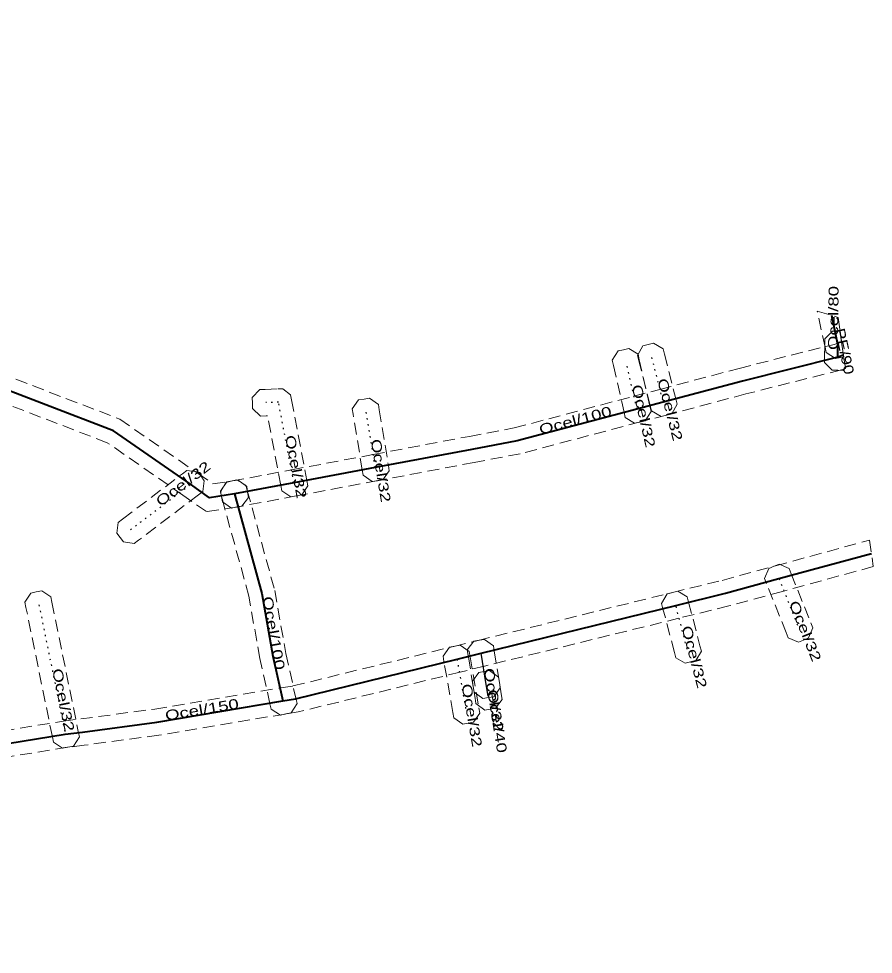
# Model space of a CAD drawing. Extents: x -583333 to -583115, y -1209681 to -1209498.
# Drawn here: x -583179.8 to -583115.3, y -1209573.7 to -1209503.1 of the extents above; entities that cross this region are included whole.
import ezdxf

# ---------------------------------------------------------------- set-up
doc = ezdxf.new("R2010")
doc.units = 0
doc.header["$LTSCALE"] = 0.3
doc.linetypes.add('DOTTED', pattern=[1.5, 0.3, -1.2])
doc.linetypes.add('MEDIUM_DASHED', pattern=[4.5, 3, -1.5])
for name, color, linetype, lineweight in [('1', 7, 'MEDIUM_DASHED', 13), ('14', 7, 'Continuous', 40), ('18', 7, 'DOTTED', 25)]:
    doc.layers.add(name, color=color, linetype=linetype, lineweight=lineweight)
doc.layers.add('20', color=7, linetype='Continuous')

msp = doc.modelspace()

# ---------------------------------------------------------------- linework, layer by layer
at = {"layer": '1'}
for points in [[(-583117.931, -1209525.643), (-583117.511, -1209528.621), (-583117.729, -1209528.668), (-583118.134, -1209528.755), (-583118.831, -1209528.306), (-583118.918, -1209527.901), (-583119.505, -1209525.173)], [(-583117.783, -1209526.692), (-583117.388, -1209529.489), (-583117.547, -1209529.644), (-583117.961, -1209529.64), (-583118.375, -1209529.635), (-583118.954, -1209529.043), (-583118.95, -1209528.629), (-583118.94, -1209527.679), (-583118.935, -1209527.265), (-583118.343, -1209526.686), (-583117.929, -1209526.69)], [(-583118.234, -1209527.68), (-583117.671, -1209527.488), (-583117.386, -1209529.504), (-583117.666, -1209529.6), (-583124.899, -1209531.428), (-583130.894, -1209533.017), (-583132.864, -1209533.537), (-583141.95, -1209535.946), (-583145.405, -1209536.593), (-583152.695, -1209537.973), (-583158.846, -1209539.123), (-583163.326, -1209539.963), (-583163.733, -1209540.039), (-583164.417, -1209539.571), (-583164.493, -1209539.164), (-583164.569, -1209538.757), (-583164.101, -1209538.073), (-583163.694, -1209537.997), (-583159.214, -1209537.157), (-583153.065, -1209536.007), (-583145.775, -1209534.627), (-583142.39, -1209533.994), (-583133.376, -1209531.603), (-583131.406, -1209531.083), (-583125.401, -1209529.492)], [(-583134.003, -1209533.196), (-583134.095, -1209532.792), (-583134.895, -1209529.282), (-583134.987, -1209528.878), (-583134.546, -1209528.177), (-583134.142, -1209528.085), (-583133.738, -1209527.993), (-583133.037, -1209528.434), (-583132.945, -1209528.838), (-583132.145, -1209532.348), (-583132.053, -1209532.752), (-583132.494, -1209533.453), (-583132.898, -1209533.545), (-583133.302, -1209533.637)], [(-583131.155, -1209528.02), (-583131.052, -1209528.421), (-583130.182, -1209531.801), (-583130.078, -1209532.202), (-583130.5, -1209532.915), (-583130.901, -1209533.018), (-583131.302, -1209533.122), (-583132.015, -1209532.7), (-583132.118, -1209532.299), (-583132.988, -1209528.919), (-583133.092, -1209528.518), (-583132.67, -1209527.805), (-583132.269, -1209527.702), (-583131.868, -1209527.598)], [(-583159.935, -1209538.734), (-583160.012, -1209538.327), (-583161.013, -1209533.076), (-583161.129, -1209533.08), (-583161.543, -1209533.092), (-583162.147, -1209532.525), (-583162.16, -1209532.111), (-583162.172, -1209531.697), (-583161.605, -1209531.093), (-583161.191, -1209531.08), (-583160.221, -1209531.05), (-583159.852, -1209531.039), (-583159.277, -1209531.501), (-583159.208, -1209531.863), (-583158.048, -1209537.953), (-583157.971, -1209538.36), (-583158.436, -1209539.045), (-583158.843, -1209539.122), (-583159.25, -1209539.199)], [(-583153.799, -1209537.561), (-583153.867, -1209537.152), (-583154.557, -1209532.962), (-583154.624, -1209532.554), (-583154.141, -1209531.881), (-583153.732, -1209531.813), (-583153.324, -1209531.746), (-583152.651, -1209532.229), (-583152.583, -1209532.638), (-583151.893, -1209536.828), (-583151.826, -1209537.236), (-583152.309, -1209537.909), (-583152.718, -1209537.977), (-583153.126, -1209538.044)], [(-583172.294, -1209541.123), (-583171.963, -1209540.873), (-583167.443, -1209537.453), (-583167.113, -1209537.203), (-583166.293, -1209537.316), (-583166.043, -1209537.647), (-583165.793, -1209537.977), (-583165.906, -1209538.797), (-583166.237, -1209539.047), (-583170.757, -1209542.467), (-583171.087, -1209542.717), (-583171.907, -1209542.604), (-583172.157, -1209542.273), (-583172.407, -1209541.943)], [(-583162.655, -1209538.316), (-583162.546, -1209538.715), (-583160.473, -1209546.271), (-583159.639, -1209551.024), (-583158.884, -1209554.391), (-583158.793, -1209554.795), (-583159.237, -1209555.495), (-583159.641, -1209555.586), (-583160.045, -1209555.677), (-583160.745, -1209555.233), (-583160.836, -1209554.829), (-583161.601, -1209551.416), (-583162.427, -1209546.709), (-583164.474, -1209539.245), (-583164.584, -1209538.845), (-583164.174, -1209538.125), (-583163.775, -1209538.016), (-583163.375, -1209537.906)], [(-583121.625, -1209544.615), (-583121.471, -1209544.999), (-583119.991, -1209548.709), (-583119.838, -1209549.094), (-583120.165, -1209549.855), (-583120.549, -1209550.009), (-583120.934, -1209550.162), (-583121.695, -1209549.835), (-583121.849, -1209549.451), (-583123.329, -1209545.741), (-583123.482, -1209545.356), (-583123.155, -1209544.595), (-583122.771, -1209544.441), (-583122.386, -1209544.288)], [(-583177.383, -1209546.754), (-583177.3, -1209547.16), (-583175.31, -1209556.92), (-583175.227, -1209557.326), (-583175.684, -1209558.017), (-583176.09, -1209558.1), (-583176.496, -1209558.183), (-583177.187, -1209557.726), (-583177.27, -1209557.32), (-583179.26, -1209547.56), (-583179.343, -1209547.154), (-583178.886, -1209546.463), (-583178.48, -1209546.38), (-583178.074, -1209546.297)], [(-583130.193, -1209551.343), (-583130.298, -1209550.942), (-583131.158, -1209547.642), (-583131.262, -1209547.241), (-583130.843, -1209546.527), (-583130.442, -1209546.422), (-583130.041, -1209546.318), (-583129.327, -1209546.737), (-583129.222, -1209547.138), (-583128.362, -1209550.438), (-583128.258, -1209550.839), (-583128.677, -1209551.553), (-583129.078, -1209551.658), (-583129.479, -1209551.762)], [(-583145.796, -1209550.88), (-583145.725, -1209551.288), (-583145.055, -1209555.128), (-583144.984, -1209555.536), (-583145.46, -1209556.214), (-583145.868, -1209556.285), (-583146.276, -1209556.356), (-583146.954, -1209555.88), (-583147.025, -1209555.472), (-583147.695, -1209551.632), (-583147.766, -1209551.224), (-583147.29, -1209550.546), (-583146.882, -1209550.475), (-583146.474, -1209550.404)], [(-583145.421, -1209553.938), (-583145.487, -1209553.529), (-583145.867, -1209551.169), (-583145.933, -1209550.76), (-583145.448, -1209550.089), (-583145.039, -1209550.023), (-583144.63, -1209549.957), (-583143.959, -1209550.442), (-583143.893, -1209550.851), (-583143.513, -1209553.211), (-583143.447, -1209553.62), (-583143.932, -1209554.291), (-583144.341, -1209554.357), (-583144.75, -1209554.423)], [(-583145.281, -1209554.808), (-583145.347, -1209554.399), (-583145.487, -1209553.529), (-583145.553, -1209553.12), (-583145.068, -1209552.449), (-583144.659, -1209552.383), (-583144.25, -1209552.317), (-583143.579, -1209552.802), (-583143.513, -1209553.211), (-583143.373, -1209554.081), (-583143.307, -1209554.49), (-583143.792, -1209555.161), (-583144.201, -1209555.227), (-583144.61, -1209555.293)]]:
    msp.add_lwpolyline(points, close=True, dxfattribs=at)
for points in [[(-583182.541, -1209529.347), (-583172.179, -1209533.33), (-583166.269, -1209537.429), (-583165.144, -1209538.212), (-583163.657, -1209537.991), (-583163.247, -1209537.93), (-583162.582, -1209538.423), (-583162.521, -1209538.833), (-583162.46, -1209539.243), (-583162.953, -1209539.908), (-583163.363, -1209539.969), (-583165.636, -1209540.308), (-583167.411, -1209539.071), (-583173.121, -1209535.11), (-583183.259, -1209531.213)], [(-583186.367, -1209557.751), (-583176.432, -1209556.13), (-583175.128, -1209555.968), (-583169.519, -1209555.221), (-583160.02, -1209553.623), (-583159.097, -1209553.479), (-583146.949, -1209550.489), (-583145.119, -1209550.039), (-583130.428, -1209546.419), (-583126.681, -1209545.502), (-583122.663, -1209544.405), (-583115.556, -1209542.465), (-583115.275, -1209544.461), (-583122.137, -1209546.335), (-583126.179, -1209547.438), (-583129.952, -1209548.361), (-583144.641, -1209551.981), (-583146.471, -1209552.431), (-583158.703, -1209555.441), (-583159.7, -1209555.597), (-583169.221, -1209557.199), (-583174.872, -1209557.952), (-583176.148, -1209558.11), (-583186.073, -1209559.729)]]:
    msp.add_lwpolyline(points, dxfattribs=at)
at = {"layer": '14'}
for p, q in [((-583117.94, -1209527.69), (-583118.412, -1209525.5)), ((-583117.95, -1209528.64), (-583117.94, -1209527.69))]:
    msp.add_line(p, q, dxfattribs=at)
at = {"layer": '14', "lineweight": 25}
for p, q in [((-583144.5, -1209553.37), (-583144.88, -1209551.01)), ((-583144.36, -1209554.24), (-583144.5, -1209553.37))]:
    msp.add_line(p, q, dxfattribs=at)
at = {"layer": '14'}
for points in [[(-583163.51, -1209538.98), (-583165.39, -1209539.26), (-583166.84, -1209538.25), (-583172.65, -1209534.22), (-583182.9, -1209530.28), (-583185.03, -1209529.46), (-583187.5, -1209528.51), (-583193.36, -1209517.78), (-583193.87, -1209516.69), (-583195.37, -1209513.48), (-583200.24, -1209503.09)], [(-583117.528, -1209528.496), (-583117.95, -1209528.64), (-583125.15, -1209530.46), (-583131.15, -1209532.05), (-583133.12, -1209532.57), (-583142.17, -1209534.97), (-583145.59, -1209535.61), (-583152.88, -1209536.99), (-583159.03, -1209538.14), (-583163.51, -1209538.98)], [(-583163.51, -1209538.98), (-583161.45, -1209546.49), (-583160.62, -1209551.22), (-583159.86, -1209554.61)], [(-583219.79, -1209573.74), (-583210.66, -1209568.63), (-583207.423, -1209565.998), (-583200.94, -1209563.12), (-583189.87, -1209559.23), (-583186.22, -1209558.74), (-583176.29, -1209557.12), (-583175, -1209556.96), (-583169.37, -1209556.21), (-583159.86, -1209554.61), (-583158.9, -1209554.46), (-583146.71, -1209551.46), (-583144.88, -1209551.01), (-583130.19, -1209547.39), (-583126.43, -1209546.47), (-583122.4, -1209545.37), (-583115.415, -1209543.463)]]:
    msp.add_lwpolyline(points, dxfattribs=at)
at = {"layer": '18'}
for p, q in [((-583132.02, -1209528.67), (-583131.15, -1209532.05)), ((-583133.12, -1209532.57), (-583133.92, -1209529.06)), ((-583152.88, -1209536.99), (-583153.57, -1209532.8)), ((-583171.36, -1209541.67), (-583166.84, -1209538.25)), ((-583122.4, -1209545.37), (-583120.92, -1209549.08)), ((-583178.28, -1209547.36), (-583176.29, -1209557.12)), ((-583129.33, -1209550.69), (-583130.19, -1209547.39)), ((-583146.71, -1209551.46), (-583146.04, -1209555.3))]:
    msp.add_line(p, q, dxfattribs=at)
msp.add_lwpolyline([(-583159.03, -1209538.14), (-583160.19, -1209532.05), (-583161.16, -1209532.08)], dxfattribs=at)

# ---------------------------------------------------------------- texts
at = {"layer": '20'}
for s, rotation, width, p in [('Ocel/80', 89.397, 1.4, (-583117.945, -1209528.115)), ('PE/90', 282.156, 1.3, (-583118.186, -1209526.546)), ('Ocel/32', 282.84, 1.4, (-583133.52, -1209530.815)), ('Ocel/32', 284.434, 1.4, (-583131.585, -1209530.36)), ('Ocel/100', 14.853, 1.4, (-583140.398, -1209534.5)), ('Ocel/32', 280.784, 1.4, (-583159.701, -1209534.618)), ('Ocel/32', 279.351, 1.4, (-583153.225, -1209534.895)), ('Ocel/32', 37.113, 1.4, (-583169.1, -1209539.96)), ('Ocel/100', 279.953, 1.4, (-583161.399, -1209546.78)), ('Ocel/32', 291.748, 1.4, (-583121.66, -1209547.225)), ('Ocel/32', 284.607, 1.4, (-583129.76, -1209549.04)), ('Ocel/32', 281.524, 1.4, (-583177.285, -1209552.24)), ('Ocel/32', 279.147, 1.4, (-583144.69, -1209552.19)), ('Ocel/32', 279.897, 1.4, (-583146.375, -1209553.38)), ('Ocel/40', 279.142, 1.4, (-583144.43, -1209553.805)), ('Ocel/150', 9.55, 1.4, (-583168.687, -1209556.095))]:
    msp.add_text(s, height=0.75, rotation=rotation, dxfattribs=dict(at, width=width)).set_placement(p)

doc.saveas('drawing.dxf')
